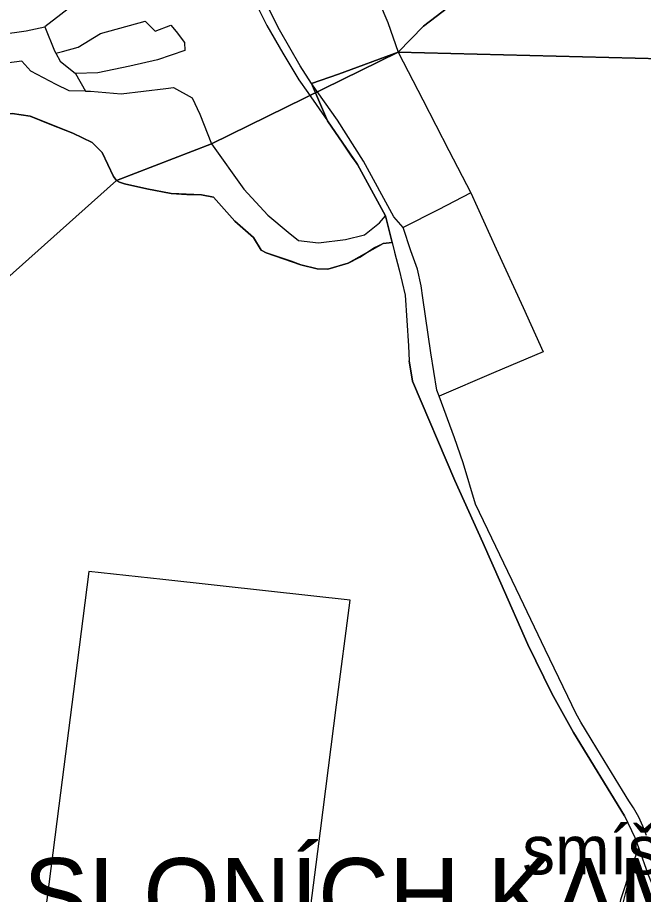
# Model space of a CAD drawing. Extents: x -706771 to -698463, y -971709 to -967107.
# Drawn here: x -702542 to -702031, y -968504 to -967788 of the extents above; entities that cross this region are included whole.
import ezdxf

# ---------------------------------------------------------------- set-up
doc = ezdxf.new("R2010")
doc.units = 0
for name, color, linetype in [('_KRAJINNY CELEK', 7, 'Continuous'), ('_KRAJINNY OKRSEK', 7, 'Continuous'), ('_KRAJINNY OKRSEK_popis', 7, 'Continuous'), ('KN_Hranice_parcel', 7, 'Continuous'), ('Prvky nelesni zeleně vhodné k zařazení do vyšší ochrany N', 7, 'Continuous'), ('Prvky nelesni zeleně vhodné k zařazení do vyšší ochrany_popis N', 7, 'Continuous'), ('Typ krajiny běžné 5L5', 7, 'Continuous'), ('Typ krajiny běžné 5M2', 7, 'Continuous')]:
    doc.layers.add(name, color=color, linetype=linetype)

msp = doc.modelspace()

# ---------------------------------------------------------------- linework, layer by layer
at = {"layer": '_KRAJINNY CELEK'}
for points in [[(-702546.17, -967865.98), (-702531.51, -967868.36), (-702496.51, -967882.21), (-702480.81, -967889.81), (-702472.57, -967898.03), (-702463.45, -967917.61), (-702461.02, -967920.78), (-702458.49, -967922.22), (-702454.44, -967923.6), (-702436.29, -967927.49), (-702416.43, -967931.27), (-702391.56, -967932.6), (-702381.87, -967934.49), (-702364.4, -967953.91), (-702349.16, -967967.23), (-702342.68, -967977.74), (-702338.6, -967979.85), (-702318.4, -967986.5), (-702310.48, -967989.61), (-702297.2, -967992.76), (-702288.43, -967993.19), (-702271.62, -967988.3), (-702243.23, -967972.07), (-702235.91, -967971.44), (-702241.33, -967949.59), (-702264.04, -967907.64), (-702288.72, -967871.93), (-702301.62, -967841.59), (-702279.53, -967833.94), (-702230.86, -967816.04), (-702210.18, -967794.78), (-702184.77, -967775.32)], [(-702184.77, -967775.32), (-702210.18, -967794.78), (-702230.86, -967816.04), (-702279.53, -967833.94), (-702301.62, -967841.59), (-702288.72, -967871.93), (-702264.04, -967907.64), (-702241.33, -967949.59), (-702235.91, -967971.44), (-702243.23, -967972.07), (-702271.62, -967988.3), (-702288.43, -967993.19), (-702297.2, -967992.76), (-702310.48, -967989.61), (-702318.4, -967986.5), (-702338.6, -967979.85), (-702342.68, -967977.74), (-702349.16, -967967.23), (-702364.4, -967953.91), (-702381.87, -967934.49), (-702391.56, -967932.6), (-702416.43, -967931.27), (-702436.29, -967927.49), (-702454.44, -967923.6), (-702458.49, -967922.22), (-702461.02, -967920.78), (-702463.45, -967917.61), (-702472.57, -967898.03), (-702480.81, -967889.81), (-702496.51, -967882.21), (-702531.51, -967868.36), (-702546.17, -967865.98)]]:
    msp.add_lwpolyline(points, dxfattribs=at)
at = {"layer": '_KRAJINNY OKRSEK'}
for p, q in [((-702184.77, -967775.32), (-702210.18, -967794.78)), ((-702230.86, -967816.04), (-702210.18, -967794.78)), ((-702210.18, -967794.78), (-702230.86, -967816.04)), ((-702279.53, -967833.94), (-702230.86, -967816.04)), ((-702230.86, -967816.04), (-702279.53, -967833.94)), ((-702301.62, -967841.59), (-702279.53, -967833.94)), ((-702279.53, -967833.94), (-702301.62, -967841.59)), ((-702301.62, -967841.59), (-702288.72, -967871.93)), ((-702496.51, -967882.21), (-702531.51, -967868.36)), ((-702288.72, -967871.93), (-702264.04, -967907.64)), ((-702480.81, -967889.81), (-702496.51, -967882.21)), ((-702264.04, -967907.64), (-702241.33, -967949.59)), ((-702416.43, -967931.27), (-702436.29, -967927.49)), ((-702364.4, -967953.91), (-702381.87, -967934.49)), ((-702243.23, -967972.07), (-702271.62, -967988.3)), ((-702318.4, -967986.5), (-702310.48, -967989.61)), ((-702310.48, -967989.61), (-702318.4, -967986.5)), ((-702310.48, -967989.61), (-702297.2, -967992.76)), ((-702271.62, -967988.3), (-702288.43, -967993.19))]:
    msp.add_line(p, q, dxfattribs=at)
for points in [[(-702210.18, -967794.78), (-702184.77, -967775.32), (-702132.22, -967735.21)], [(-702243.23, -967972.07), (-702235.91, -967971.44), (-702241.33, -967949.59), (-702264.04, -967907.64), (-702288.72, -967871.93), (-702301.62, -967841.59)], [(-702627.65, -967887.27), (-702602.14, -967876.99), (-702594.7, -967874.76), (-702567.58, -967867.59), (-702546.17, -967865.98), (-702531.51, -967868.36), (-702496.51, -967882.21), (-702480.81, -967889.81)], [(-702531.51, -967868.36), (-702546.17, -967865.98), (-702567.58, -967867.59)], [(-702480.81, -967889.81), (-702472.57, -967898.03), (-702463.45, -967917.61)], [(-702463.45, -967917.61), (-702472.57, -967898.03), (-702480.81, -967889.81)], [(-702463.45, -967917.61), (-702461.02, -967920.78), (-702458.49, -967922.22)], [(-702458.49, -967922.22), (-702461.02, -967920.78), (-702463.45, -967917.61)], [(-702458.49, -967922.22), (-702454.44, -967923.6), (-702436.29, -967927.49), (-702416.43, -967931.27), (-702391.56, -967932.6), (-702381.87, -967934.49)], [(-702436.29, -967927.49), (-702454.44, -967923.6), (-702458.49, -967922.22)], [(-702381.87, -967934.49), (-702391.56, -967932.6), (-702416.43, -967931.27)], [(-702381.87, -967934.49), (-702364.4, -967953.91), (-702349.16, -967967.23)], [(-702241.33, -967949.59), (-702235.91, -967971.44), (-702243.23, -967972.07)], [(-702342.68, -967977.74), (-702349.16, -967967.23), (-702364.4, -967953.91)], [(-702349.16, -967967.23), (-702342.68, -967977.74), (-702338.6, -967979.85), (-702318.4, -967986.5)], [(-702297.2, -967992.76), (-702288.43, -967993.19), (-702271.62, -967988.3), (-702243.23, -967972.07)], [(-702318.4, -967986.5), (-702338.6, -967979.85), (-702342.68, -967977.74)], [(-702288.43, -967993.19), (-702297.2, -967992.76), (-702310.48, -967989.61)]]:
    msp.add_lwpolyline(points, dxfattribs=at)
at = {"layer": 'KN_Hranice_parcel'}
for p, q in [((-702494.44, -967833.47), (-702486.36, -967847.86)), ((-702241.33, -967949.59), (-702235.91, -967971.44))]:
    msp.add_line(p, q, dxfattribs=at)
for points in [[(-702387.34, -967663.54), (-702370.4, -967657), (-702346.5, -967655.79), (-702320.24, -967658.5), (-702295.14, -967666.59), (-702287.52, -967674.84), (-702281.73, -967684.2), (-702273.2, -967703.16), (-702263.55, -967732.41), (-702252.68, -967760.29), (-702239.33, -967791.7), (-702230.86, -967816.04)], [(-702226.72, -967959.13), (-702234.57, -967950.53), (-702259.21, -967905.02), (-702280.35, -967871.49), (-702301.62, -967841.59), (-702310.82, -967827.27), (-702327.85, -967797.81), (-702335, -967783.75), (-702345.98, -967758.97), (-702347.68, -967755.25), (-702352.03, -967746.75), (-702358.94, -967732.43), (-702364.68, -967717.6), (-702374.4, -967689.1), (-702376.69, -967682.65), (-702381.91, -967671.65), (-702387.34, -967663.54)], [(-702392.01, -967666.51), (-702387.02, -967674.72), (-702383.23, -967686.75), (-702377.01, -967706.45), (-702365.51, -967735.59), (-702355.16, -967757.02), (-702346.66, -967777.28), (-702338.22, -967794.31), (-702325.11, -967816.74), (-702312.06, -967838.5), (-702304.75, -967848.95), (-702288.72, -967871.93), (-702268.84, -967901.65), (-702264.04, -967907.64), (-702241.33, -967949.59)], [(-702458.33, -967704.36), (-702446.05, -967733.87), (-702445.94, -967739.12), (-702461.99, -967752.17), (-702482.03, -967766.92), (-702494.56, -967776.07), (-702506.44, -967785.18), (-702519.58, -967795.34)], [(-702230.86, -967816.04), (-702210.18, -967794.78), (-702184.77, -967775.32)], [(-702510.4, -967816.92), (-702505.04, -967815.35), (-702492.31, -967811.96), (-702473.97, -967800.81), (-702437.65, -967790.67), (-702429.36, -967798.78), (-702416.6, -967793.93), (-702412.3, -967799.12), (-702405.46, -967808.01), (-702405.13, -967814.59), (-702427.39, -967822.35), (-702449.97, -967827.29), (-702476.09, -967832.91), (-702494.44, -967833.47)], [(-702653.04, -967798.06), (-702648.1, -967803.29), (-702642.77, -967809.63), (-702621.32, -967811.23), (-702597.62, -967811.21), (-702575, -967807.21), (-702556.12, -967801.58), (-702534.7, -967798.6), (-702519.58, -967795.34)], [(-702519.58, -967795.34), (-702511.55, -967814.81), (-702510.4, -967816.92)], [(-702510.4, -967816.92), (-702506.94, -967823.24), (-702494.44, -967833.47)], [(-702230.86, -967816.04), (-702210.76, -967855.04), (-702189.51, -967896.27), (-702171.66, -967930.91)], [(-702486.36, -967847.86), (-702499.62, -967847.58), (-702510.26, -967842.49), (-702531, -967831.54), (-702538.38, -967823.39), (-702553.01, -967825.3), (-702572.31, -967828.14), (-702579.65, -967830.91), (-702583.91, -967829.92), (-702595.58, -967829.51), (-702621.41, -967829.53), (-702639.07, -967827.29), (-702643.86, -967825.8), (-702663.03, -967827.72), (-702668.83, -967827.49), (-702669.94, -967822.77)], [(-702486.36, -967847.86), (-702482.18, -967847.95), (-702457.09, -967849.97), (-702420.6, -967845.59), (-702414.41, -967844.91), (-702399.09, -967853.26), (-702392.88, -967866.55), (-702383.36, -967890.77), (-702356.93, -967927.82), (-702337.26, -967949.03), (-702320.65, -967963.05), (-702312.2, -967969.65), (-702296.04, -967971.7), (-702274.04, -967969.05), (-702258.28, -967965.11), (-702246.21, -967955.43), (-702241.33, -967949.59)], [(-702546.17, -967865.98), (-702531.51, -967868.36), (-702515.4, -967874.85), (-702496.51, -967882.21), (-702480.81, -967889.81), (-702472.57, -967898.03), (-702463.45, -967917.61), (-702461.02, -967920.78), (-702458.49, -967922.22), (-702454.44, -967923.6), (-702436.29, -967927.49), (-702416.43, -967931.27), (-702403.5, -967932.24), (-702391.56, -967932.6), (-702381.87, -967934.49), (-702364.4, -967953.91), (-702349.16, -967967.23), (-702342.68, -967977.74), (-702338.6, -967979.85), (-702310.48, -967989.61), (-702297.2, -967992.76), (-702288.43, -967993.19), (-702271.62, -967988.3), (-702262.25, -967983.27), (-702250.14, -967975.43), (-702243.23, -967972.07), (-702235.91, -967971.44)], [(-702171.66, -967930.91), (-702198.35, -967944.59), (-702226.72, -967959.13)], [(-702171.66, -967930.91), (-702150.75, -967976.68), (-702128.93, -968024.43), (-702112.41, -968060.6), (-702152.94, -968077.86), (-702197.5, -968096.83)], [(-702197.5, -968096.83), (-702199.32, -968091.88), (-702204.28, -968061.46), (-702210.78, -968016.67), (-702212.09, -968006.7), (-702215.18, -967993.04), (-702220.55, -967978.09), (-702226.72, -967959.13)], [(-702235.91, -967971.44), (-702233.97, -967979.28), (-702230.11, -967993.61), (-702225.2, -968014.32), (-702222.5, -968055.81), (-702221.96, -968068.07), (-702219.19, -968084.67), (-702184.59, -968165.74), (-702161.89, -968216.27), (-702147.07, -968249.45), (-702125.02, -968299.5), (-702105.34, -968339.53), (-702087.76, -968371.4), (-702046, -968439.5), (-702037.59, -968457.14), (-702034.7, -968465.27)], [(-702028.13, -968455.39), (-702031.01, -968447.89), (-702034.46, -968440.6), (-702038.83, -968433.03), (-702042.48, -968427.08), (-702047.64, -968418.66), (-702068.64, -968384.4), (-702077.91, -968369.29), (-702081.74, -968362.95), (-702085.76, -968355.74), (-702092.46, -968342.13), (-702110.9, -968303.57), (-702131.3, -968260.93), (-702167.68, -968184.88), (-702177.86, -968151.32), (-702184.92, -968130.81), (-702197.5, -968096.83)], [(-702312.59, -968594.17), (-702305.71, -968540.38), (-702294.36, -968451.71), (-702281.17, -968348.69), (-702270.25, -968263.34), (-702336.91, -968256.05), (-702423.2, -968246.61), (-702483.69, -968240), (-702494.86, -968327.45), (-702508.11, -968431.21), (-702519.54, -968520.79), (-702527.91, -968586.3)], [(-702034.7, -968465.27), (-702035.77, -968468.85), (-702040.59, -968481.56)], [(-702034.7, -968465.27), (-702026.73, -968487.68), (-702000.63, -968550), (-701967.64, -968635.12), (-701943.54, -968697.32), (-701937.36, -968716.03), (-701933.97, -968731.44)], [(-702040.59, -968481.56), (-702049.28, -968507.88), (-702053.69, -968526.88), (-702057.5, -968549.49), (-702059.7, -968570.45)], [(-702049.66, -968570.1), (-702053.67, -968558.01), (-702054.63, -968551.21), (-702052.12, -968531.63), (-702046.91, -968509.77), (-702042.93, -968494.36), (-702040.59, -968481.56)]]:
    msp.add_lwpolyline(points, dxfattribs=at)
at = {"layer": 'Prvky nelesni zeleně vhodné k zařazení do vyšší ochrany N'}
msp.add_lwpolyline([(-702046, -968439.5), (-702087.76, -968371.4), (-702105.34, -968339.53), (-702125.02, -968299.5), (-702147.07, -968249.45), (-702161.89, -968216.27), (-702184.59, -968165.74), (-702219.19, -968084.67), (-702221.96, -968068.07)], dxfattribs=at)
at = {"layer": 'Typ krajiny běžné 5L5'}
msp.add_line((-702949.59, -968356.19), (-702461.02, -967920.78), dxfattribs=at)
msp.add_lwpolyline([(-702461.02, -967920.78), (-702383.36, -967890.77), (-702230.86, -967816.04), (-701908.36, -967824.2)], dxfattribs=at)
at = {"layer": 'Typ krajiny běžné 5M2'}
msp.add_line((-702461.02, -967920.78), (-702949.59, -968356.19), dxfattribs=at)
msp.add_lwpolyline([(-701908.36, -967824.2), (-702230.86, -967816.04), (-702383.36, -967890.77), (-702461.02, -967920.78)], dxfattribs=at)

# ---------------------------------------------------------------- texts
at = {"layer": '_KRAJINNY OKRSEK_popis'}
msp.add_text('U SLONÍCH KAMENŮ', height=60, dxfattribs=at).set_placement((-702617.37, -968533.95))
at = {"layer": 'Prvky nelesni zeleně vhodné k zařazení do vyšší ochrany_popis N'}
msp.add_text('smíšená alej', height=40, dxfattribs=at).set_placement((-702129.57, -968487.29))

doc.saveas('drawing.dxf')
